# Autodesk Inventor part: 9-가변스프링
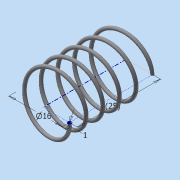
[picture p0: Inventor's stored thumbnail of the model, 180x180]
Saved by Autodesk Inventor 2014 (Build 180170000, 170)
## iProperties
Created: 2015-06
Part Number: 9-가변스프링
Material: 강철, 연강
Document SubType Name: Modeling
Designer: Administrator
Density: 7.86 g/cm^3
Appearance: 강철
Mass: 1.52988 g
Surface Area: 7.87024 cm^2
Volume: 0.194641 cm^3
Author: Administrator
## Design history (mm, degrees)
sketch "스케치1"
  geometry: L1 (0, 0)-(8, 0); L2 (8, 0)-(8, 14.5); L3 (8, 14.5)-(0, 14.5); L4 (0, 14.5)-(0, 0); C1 r 0.5 at (8, 0)
  constraints: 8 end point, 2 parallel, 1 centre point, 1 coincident, 1 horizontal, 1 perpendicular
  dimensions: "d0" = 1 diameter of C1; "d1" = 16 diameter of L2 L4; "d2" = 14.5 distance of L1.end L2.end (derived)
feature "코일1" sketch "스케치1" pitch "d3" = 10; turns "d5" = 5; dims "d4" = 14.5 (= d2), "d6" = 0, angle "d7" = 90 deg, angle "d8" = 90 deg, "d9" = 0, "d10" = 0
sketch "스케치2"
  geometry: L1 (-8.5, 0)-(-7.5, 0) reference; 1 further point
  constraints: 1 horizontal alignment
extrude "돌출1" cut sketch "스케치2" distance "d11" = 10; taper "d12" = 0 deg
node "작업 평면1"
sketch "스케치3"
  geometry: L1 (-7.5, 0)-(-8.5, 0) reference; 1 further point
  constraints: 1 horizontal alignment
extrude "돌출2" cut sketch "스케치3" distance "d14" = 10; taper "d15" = 0 deg
node "솔리드1"
node "절단 모서리 투영1"
node "절단 모서리 투영2"
other parameters: "d13" = 14.5 (= d2)
